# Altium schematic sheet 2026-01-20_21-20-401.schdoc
size 345 x 144 mm; SheetNumber: 1; SheetTotal: 1
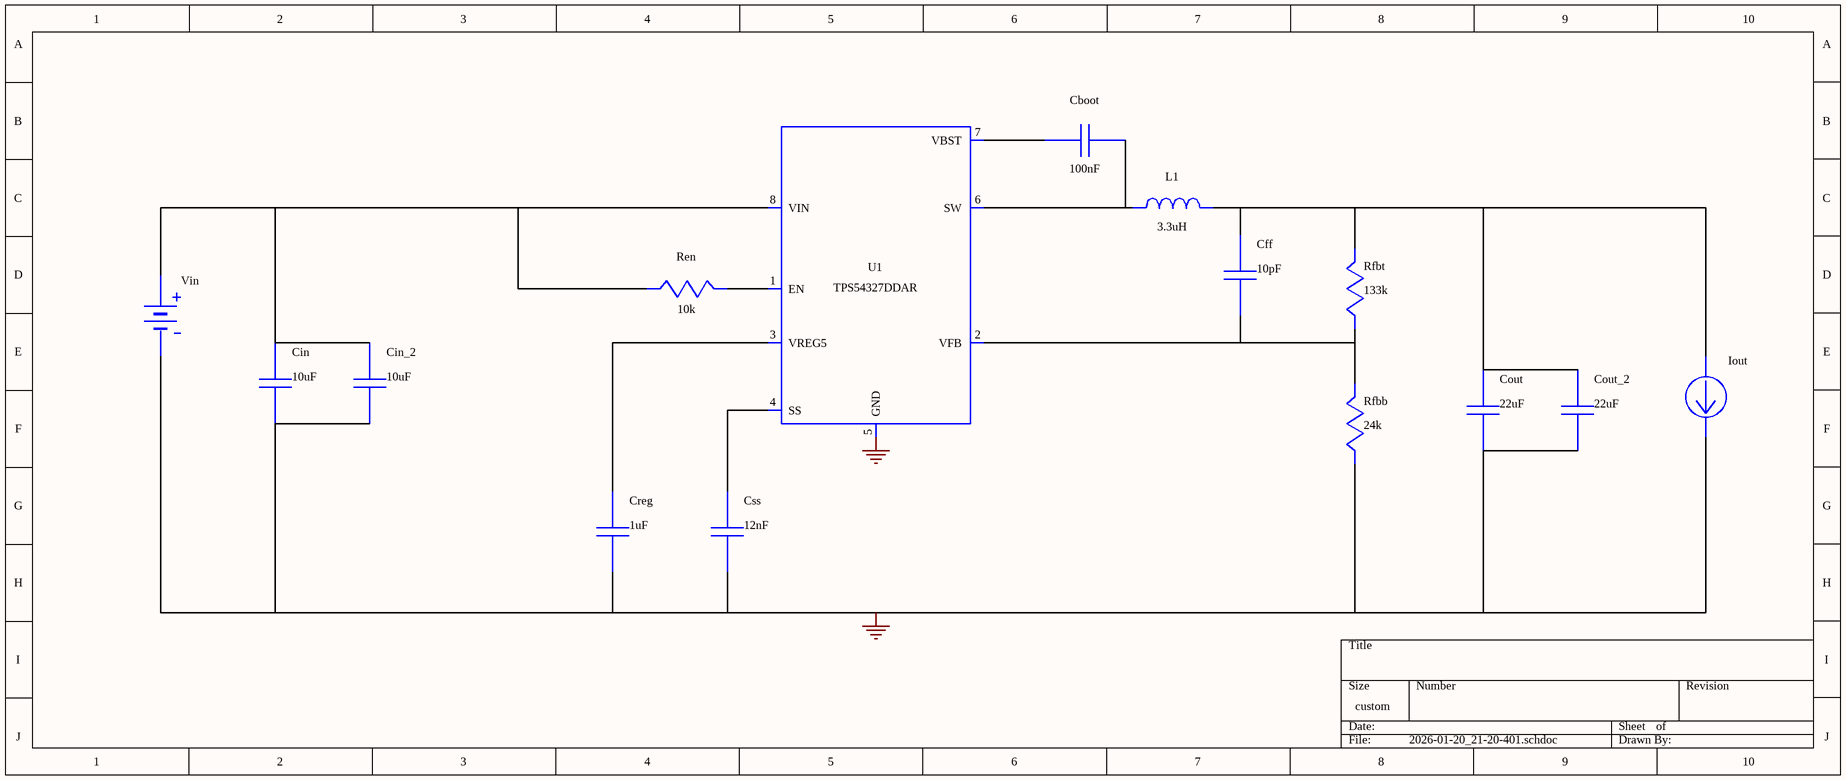
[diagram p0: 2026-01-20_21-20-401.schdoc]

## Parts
Cboot  value 100nF  (hidden comment: 08053C104KAT2A)
Cff  value 10pF  (hidden comment: C0805C100M4GACTU)
Cin  value 10uF  (hidden comment: GRM32ER71J106KA12L)
Cin_2  value 10uF  (hidden comment: GRM32ER71J106KA12L)
Cout  value 22uF  (hidden comment: C3216X5R1C226M160AB)
Cout_2  value 22uF  (hidden comment: C3216X5R1C226M160AB)
Creg  value 1uF  (hidden comment: C0603C105Z8VACTU)
Css  value 12nF  (hidden comment: GRM033C80J123KE01D)
Iout  WB_CURRENT_LOAD  (value not drawn)
L1  value 3.3uH  (hidden comment: VLP8040T-3R3N)
Ren  value 10k  (hidden comment: RC0201FR-0710KL)
Rfbb  value 24k  (hidden comment: RC0603FR-0724KL)
Rfbt  value 133k  (hidden comment: RC0201FR-07133KL)
U1  TPS54327DDAR
Vin  WB_BATTERY  (value not drawn)

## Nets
0: Cin.2 Cin_2.2 Cout.2 Cout_2.2 Creg.2 Css.2 Iout.2(-) Rfbb.2 U1.5(GND) U1.9(ETPAD) Vin.2(-)
NetCboot_1: Cboot.1 U1.7(VBST)
NetCboot_2: Cboot.2 L1.2 U1.6(SW)
NetCff_1: Cff.1 Cout.1 Cout_2.1 Iout.1(+) L1.1 Rfbt.1
NetCff_2: Cff.2 Rfbb.1 Rfbt.2 U1.2(VFB)
NetCin_1: Cin.1 Cin_2.1 Ren.2 U1.8(VIN) Vin.1(+)
NetCreg_1: Creg.1 U1.3(VREG5)
NetCss_1: Css.1 U1.4(SS)
NetRen_1: Ren.1 U1.1(EN)

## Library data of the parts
Cboot = 08053C104KAT2A: Manufacturer Name: AVX
Cff = C0805C100M4GACTU: Manufacturer Name: Kemet
Cin Cin_2 = GRM32ER71J106KA12L: GRM32ER71J106KA1; Manufacturer Name: MuRata
Cout Cout_2 = C3216X5R1C226M160AB: C3216X5R1C226M16; Manufacturer Name: TDK
Creg = C0603C105Z8VACTU: Manufacturer Name: Kemet
Css = GRM033C80J123KE01D: GRM033C80J123KE0; Manufacturer Name: MuRata
L1 = VLP8040T-3R3N: Unknown; Manufacturer Name: TDK
Ren = RC0201FR-0710KL: Manufacturer Name: Yageo
Rfbb = RC0603FR-0724KL: Manufacturer Name: Yageo
Rfbt = RC0201FR-07133KL: Manufacturer Name: Yageo
U1 = TPS54327DDAR: Manufacturer Name: Texas Instruments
